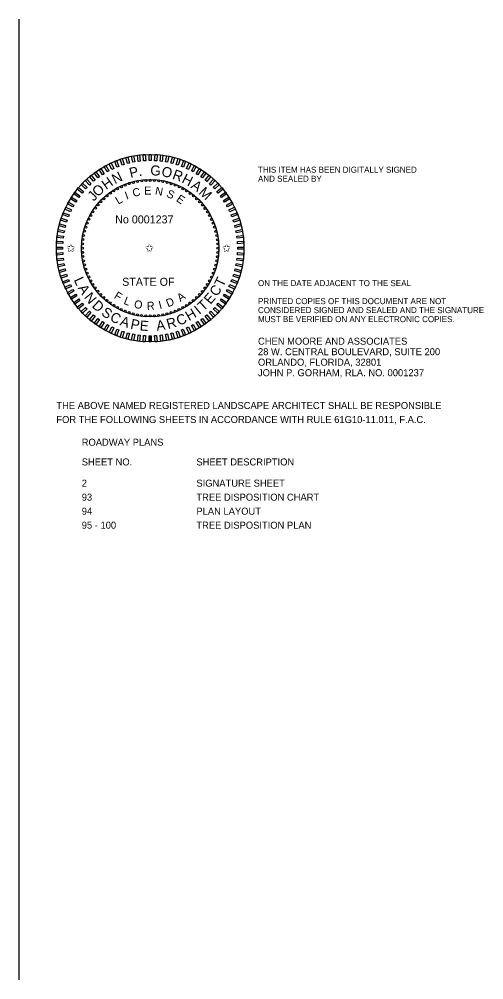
# Model space of a CAD drawing. Extents: x -811 to 10319, y -2309 to 9962.
# Drawn here: x -803.09 to -798.44, y -2187.21 to -2177.61 of the extents above; entities that cross this region are included whole.
import ezdxf

# ---------------------------------------------------------------- set-up
doc = ezdxf.new("R2010")
doc.units = 0
for name, color, linetype in [('PlotBorder_dp', 7, 'Continuous'), ('TextMinor', 7, 'Continuous'), ('TextMisc', 7, 'Continuous'), ('TextNotes', 7, 'Continuous'), ('TextShtNo', 7, 'Continuous')]:
    doc.layers.add(name, color=color, linetype=linetype)

msp = doc.modelspace()

# ---------------------------------------------------------------- linework, layer by layer
at = {"layer": 'TextMinor'}
for radius in [0.9375, 0.6875]:
    msp.add_circle((-801.777, -2179.9009), radius, dxfattribs=at)
at = {"layer": 'TextNotes'}
msp.add_line((-803.0858, -2187.2129), (-803.0858, -2177.6129), dxfattribs=at)
at = {"layer": 'TextShtNo'}
for p, q in [((-801.787, -2180.8384), (-801.7871, -2180.7759)), ((-801.777, -2180.8384), (-801.7771, -2180.7759)), ((-801.767, -2180.8383), (-801.7671, -2180.7758))]:
    msp.add_line(p, q, dxfattribs=at)
for points in [[(-802.0377, -2179.0655), (-802.0569, -2179.0718), (-802.0762, -2179.0124), (-802.057, -2179.0061)], [(-801.9847, -2179.0508), (-802.0042, -2179.0558), (-802.0198, -2178.9953), (-802.0002, -2178.9903)], [(-801.9309, -2179.0394), (-801.9507, -2179.0432), (-801.9624, -2178.9819), (-801.9426, -2178.9781)], [(-801.8765, -2179.0315), (-801.8965, -2179.034), (-801.9044, -2178.972), (-801.8843, -2178.9695)], [(-801.8217, -2179.0269), (-801.8419, -2179.0282), (-801.8458, -2178.9659), (-801.8256, -2178.9646)], [(-801.7668, -2179.0258), (-801.787, -2179.0258), (-801.787, -2178.9634), (-801.7668, -2178.9634)], [(-801.7118, -2179.0282), (-801.732, -2179.0269), (-801.7281, -2178.9646), (-801.7079, -2178.9659)], [(-801.6572, -2179.034), (-801.6772, -2179.0315), (-801.6694, -2178.9695), (-801.6493, -2178.9721)], [(-801.603, -2179.0432), (-801.6228, -2179.0395), (-801.6111, -2178.9781), (-801.5913, -2178.9819)], [(-801.5495, -2179.0559), (-801.569, -2179.0508), (-801.5535, -2178.9904), (-801.5339, -2178.9954)], [(-801.4969, -2179.0718), (-801.5161, -2179.0656), (-801.4968, -2179.0062), (-801.4776, -2179.0124)], [(-802.2372, -2179.1566), (-802.2543, -2179.1674), (-802.2877, -2179.1147), (-802.2707, -2179.1039)], [(-802.1896, -2179.1292), (-802.2073, -2179.1389), (-802.2373, -2179.0842), (-802.2197, -2179.0745)], [(-802.1403, -2179.1048), (-802.1586, -2179.1134), (-802.1852, -2179.0569), (-802.1669, -2179.0483)], [(-802.0896, -2179.0835), (-802.1084, -2179.091), (-802.1314, -2179.0329), (-802.1126, -2179.0255)], [(-801.4454, -2179.091), (-801.4641, -2179.0836), (-801.4411, -2179.0256), (-801.4224, -2179.033)], [(-801.3952, -2179.1135), (-801.4134, -2179.1049), (-801.3868, -2179.0484), (-801.3686, -2179.057)], [(-801.3465, -2179.139), (-801.3642, -2179.1293), (-801.3341, -2179.0745), (-801.3164, -2179.0843)], [(-801.2995, -2179.1675), (-801.3165, -2179.1567), (-801.2831, -2179.104), (-801.266, -2179.1148)], [(-802.3269, -2179.2202), (-802.3424, -2179.233), (-802.3822, -2179.1849), (-802.3667, -2179.172)], [(-802.283, -2179.187), (-802.2994, -2179.1988), (-802.3361, -2179.1483), (-802.3197, -2179.1365)], [(-801.2544, -2179.1989), (-801.2707, -2179.1871), (-801.234, -2179.1366), (-801.2177, -2179.1484)], [(-801.2113, -2179.2331), (-801.2269, -2179.2203), (-801.1871, -2179.1722), (-801.1715, -2179.185)], [(-802.4447, -2179.3353), (-802.4575, -2179.3508), (-802.5057, -2179.311), (-802.4928, -2179.2955)], [(-802.4078, -2179.2944), (-802.4217, -2179.3092), (-802.4672, -2179.2664), (-802.4534, -2179.2517)], [(-802.3685, -2179.256), (-802.3832, -2179.2698), (-802.426, -2179.2243), (-802.4113, -2179.2105)], [(-801.1705, -2179.27), (-801.1852, -2179.2562), (-801.1425, -2179.2106), (-801.1278, -2179.2245)], [(-801.1321, -2179.3093), (-801.1459, -2179.2946), (-801.1004, -2179.2518), (-801.0866, -2179.2666)], [(-801.0962, -2179.351), (-801.1091, -2179.3354), (-801.061, -2179.2956), (-801.0481, -2179.3112)], [(-802.5103, -2179.4234), (-802.5211, -2179.4404), (-802.5738, -2179.407), (-802.563, -2179.3899)], [(-802.4789, -2179.3783), (-802.4907, -2179.3946), (-802.5413, -2179.3579), (-802.5294, -2179.3416)], [(-801.063, -2179.3948), (-801.0749, -2179.3784), (-801.0244, -2179.3417), (-801.0125, -2179.3581)], [(-801.0327, -2179.4406), (-801.0435, -2179.4236), (-800.9908, -2179.3901), (-800.98, -2179.4071)], [(-802.5388, -2179.4704), (-802.5486, -2179.4881), (-802.6033, -2179.458), (-802.5936, -2179.4403)], [(-801.0052, -2179.4882), (-801.015, -2179.4706), (-800.9603, -2179.4405), (-800.9505, -2179.4582)], [(-802.5868, -2179.5693), (-802.5942, -2179.588), (-802.6523, -2179.5651), (-802.6448, -2179.5463)], [(-802.5644, -2179.5191), (-802.573, -2179.5373), (-802.6295, -2179.5108), (-802.6209, -2179.4925)], [(-800.9809, -2179.5375), (-800.9895, -2179.5193), (-800.933, -2179.4927), (-800.9244, -2179.5109)], [(-800.9596, -2179.5882), (-800.967, -2179.5695), (-800.909, -2179.5465), (-800.9016, -2179.5652)], [(-802.622, -2179.6734), (-802.627, -2179.6929), (-802.6875, -2179.6774), (-802.6824, -2179.6579)], [(-802.606, -2179.6208), (-802.6122, -2179.64), (-802.6716, -2179.6207), (-802.6654, -2179.6015)], [(-800.9416, -2179.6402), (-800.9478, -2179.621), (-800.8885, -2179.6017), (-800.8822, -2179.6209)], [(-800.9269, -2179.6931), (-800.9319, -2179.6736), (-800.8714, -2179.658), (-800.8664, -2179.6776)], [(-802.6438, -2179.7811), (-802.6463, -2179.8011), (-802.7083, -2179.7933), (-802.7058, -2179.7733)], [(-802.6346, -2179.7269), (-802.6384, -2179.7467), (-802.6997, -2179.735), (-802.6959, -2179.7152)], [(-800.9155, -2179.7469), (-800.9193, -2179.7271), (-800.858, -2179.7154), (-800.8542, -2179.7352)], [(-800.9075, -2179.8013), (-800.9101, -2179.7813), (-800.8481, -2179.7735), (-800.8456, -2179.7935)], [(-802.6496, -2179.8358), (-802.6509, -2179.8559), (-802.7132, -2179.852), (-802.7119, -2179.8318)], [(-800.903, -2179.8561), (-800.9043, -2179.8359), (-800.842, -2179.832), (-800.8407, -2179.8522)], [(-802.652, -2179.8907), (-802.652, -2179.9109), (-802.7144, -2179.9109), (-802.7144, -2179.8907)], [(-802.6509, -2179.9456), (-802.6496, -2179.9658), (-802.7119, -2179.9697), (-802.7132, -2179.9496)], [(-800.9043, -2179.966), (-800.903, -2179.9458), (-800.8407, -2179.9498), (-800.842, -2179.9699)], [(-800.9019, -2179.9111), (-800.9019, -2179.8909), (-800.8395, -2179.8909), (-800.8395, -2179.9111)], [(-802.6464, -2180.0004), (-802.6438, -2180.0205), (-802.7058, -2180.0283), (-802.7083, -2180.0083)], [(-802.6384, -2180.0548), (-802.6346, -2180.0747), (-802.6959, -2180.0864), (-802.6997, -2180.0665)], [(-800.9193, -2180.0748), (-800.9155, -2180.055), (-800.8542, -2180.0667), (-800.858, -2180.0865)], [(-800.9101, -2180.0206), (-800.9076, -2180.0006), (-800.8456, -2180.0084), (-800.8481, -2180.0285)], [(-802.627, -2180.1086), (-802.622, -2180.1282), (-802.6825, -2180.1437), (-802.6875, -2180.1241)], [(-800.9319, -2180.1283), (-800.9269, -2180.1088), (-800.8664, -2180.1243), (-800.8715, -2180.1439)], [(-802.6123, -2180.1616), (-802.6061, -2180.1808), (-802.6654, -2180.2001), (-802.6717, -2180.1809)], [(-802.5943, -2180.2135), (-802.5869, -2180.2323), (-802.6449, -2180.2553), (-802.6523, -2180.2365)], [(-800.9671, -2180.2325), (-800.9597, -2180.2137), (-800.9016, -2180.2367), (-800.9091, -2180.2554)], [(-800.9479, -2180.181), (-800.9417, -2180.1618), (-800.8823, -2180.1811), (-800.8885, -2180.2003)], [(-802.573, -2180.2642), (-802.5644, -2180.2825), (-802.6209, -2180.3091), (-802.6295, -2180.2908)], [(-802.5487, -2180.3135), (-802.5389, -2180.3312), (-802.5936, -2180.3613), (-802.6034, -2180.3436)], [(-801.0151, -2180.3313), (-801.0053, -2180.3137), (-800.9506, -2180.3437), (-800.9603, -2180.3614)], [(-800.9895, -2180.2827), (-800.9809, -2180.2644), (-800.9244, -2180.291), (-800.933, -2180.3092)], [(-802.5212, -2180.3611), (-802.5104, -2180.3782), (-802.5631, -2180.4116), (-802.5739, -2180.3946)], [(-802.4909, -2180.407), (-802.479, -2180.4233), (-802.5295, -2180.46), (-802.5414, -2180.4437)], [(-801.075, -2180.4234), (-801.0632, -2180.4071), (-801.0126, -2180.4438), (-801.0245, -2180.4601)], [(-801.0436, -2180.3783), (-801.0328, -2180.3613), (-800.9801, -2180.3947), (-800.9909, -2180.4118)], [(-802.4577, -2180.4508), (-802.4448, -2180.4663), (-802.4929, -2180.5061), (-802.5058, -2180.4906)], [(-802.4218, -2180.4924), (-802.408, -2180.5072), (-802.4535, -2180.5499), (-802.4673, -2180.5352)], [(-802.3834, -2180.5318), (-802.3687, -2180.5456), (-802.4114, -2180.5911), (-802.4261, -2180.5773)], [(-801.1854, -2180.5457), (-801.1707, -2180.5319), (-801.1279, -2180.5774), (-801.1426, -2180.5912)], [(-801.1461, -2180.5073), (-801.1322, -2180.4926), (-801.0867, -2180.5353), (-801.1005, -2180.55)], [(-801.1092, -2180.4665), (-801.0964, -2180.4509), (-801.0482, -2180.4907), (-801.0611, -2180.5063)], [(-802.3426, -2180.5686), (-802.327, -2180.5815), (-802.3668, -2180.6296), (-802.3824, -2180.6167)], [(-802.2995, -2180.6028), (-802.2832, -2180.6147), (-802.3199, -2180.6652), (-802.3362, -2180.6533)], [(-802.2544, -2180.6342), (-802.2374, -2180.645), (-802.2708, -2180.6978), (-802.2879, -2180.6869)], [(-801.3167, -2180.6451), (-801.2996, -2180.6343), (-801.2662, -2180.687), (-801.2832, -2180.6979)], [(-801.2709, -2180.6148), (-801.2545, -2180.6029), (-801.2178, -2180.6534), (-801.2342, -2180.6653)], [(-801.227, -2180.5816), (-801.2115, -2180.5687), (-801.1717, -2180.6168), (-801.1872, -2180.6297)], [(-802.2074, -2180.6628), (-802.1897, -2180.6725), (-802.2198, -2180.7272), (-802.2375, -2180.7175)], [(-802.1587, -2180.6883), (-802.1405, -2180.6969), (-802.1671, -2180.7534), (-802.1853, -2180.7448)], [(-802.1085, -2180.7107), (-802.0898, -2180.7181), (-802.1128, -2180.7762), (-802.1315, -2180.7688)], [(-802.057, -2180.7299), (-802.0378, -2180.7362), (-802.0571, -2180.7955), (-802.0763, -2180.7893)], [(-801.5162, -2180.7362), (-801.497, -2180.73), (-801.4777, -2180.7894), (-801.4969, -2180.7956)], [(-801.4643, -2180.7182), (-801.4455, -2180.7108), (-801.4225, -2180.7688), (-801.4413, -2180.7763)], [(-801.4136, -2180.697), (-801.3953, -2180.6884), (-801.3687, -2180.7449), (-801.387, -2180.7535)], [(-801.3643, -2180.6726), (-801.3466, -2180.6628), (-801.3166, -2180.7176), (-801.3342, -2180.7273)], [(-802.0044, -2180.7459), (-801.9849, -2180.7509), (-802.0004, -2180.8114), (-802.02, -2180.8064)], [(-801.9509, -2180.7585), (-801.9311, -2180.7623), (-801.9428, -2180.8236), (-801.9626, -2180.8198)], [(-801.8967, -2180.7677), (-801.8767, -2180.7703), (-801.8845, -2180.8322), (-801.9046, -2180.8297)], [(-801.8421, -2180.7735), (-801.8219, -2180.7748), (-801.8258, -2180.8371), (-801.846, -2180.8358)], [(-801.7871, -2180.7759), (-801.767, -2180.7759), (-801.767, -2180.8383), (-801.7871, -2180.8383)], [(-801.7322, -2180.7748), (-801.712, -2180.7735), (-801.7081, -2180.8359), (-801.7283, -2180.8371)], [(-801.6774, -2180.7703), (-801.6574, -2180.7677), (-801.6495, -2180.8297), (-801.6696, -2180.8322)], [(-801.623, -2180.7623), (-801.6032, -2180.7585), (-801.5915, -2180.8199), (-801.6113, -2180.8236)], [(-801.5692, -2180.7509), (-801.5497, -2180.7459), (-801.5341, -2180.8064), (-801.5537, -2180.8114)]]:
    msp.add_lwpolyline(points, close=True, dxfattribs=at)
for centre in [(-802.0649, -2179.2876), (-802.0258, -2179.2708), (-801.9858, -2179.2564), (-801.9449, -2179.2445), (-801.9033, -2179.2353), (-801.8613, -2179.2287), (-801.8189, -2179.2247), (-801.7764, -2179.2234), (-801.7338, -2179.2248), (-801.6915, -2179.2288), (-801.6495, -2179.2355), (-801.6079, -2179.2448), (-801.5671, -2179.2567), (-801.527, -2179.2712), (-801.488, -2179.2881), (-802.2084, -2179.3785), (-802.1747, -2179.3525), (-802.1395, -2179.3286), (-802.1028, -2179.3069), (-801.4501, -2179.3075), (-801.4135, -2179.3292), (-801.3783, -2179.3531), (-801.3447, -2179.3792), (-802.2986, -2179.4686), (-802.2704, -2179.4367), (-802.2403, -2179.4066), (-801.3128, -2179.4074), (-801.2827, -2179.4375), (-801.2546, -2179.4695), (-802.3703, -2179.574), (-802.3487, -2179.5374), (-802.3247, -2179.5022), (-801.2285, -2179.5031), (-801.2046, -2179.5383), (-801.183, -2179.575), (-802.4066, -2179.651), (-802.3897, -2179.6119), (-801.1637, -2179.6129), (-801.1468, -2179.652), (-802.4423, -2179.7734), (-802.433, -2179.7318), (-802.4211, -2179.691), (-801.1325, -2179.6921), (-801.1206, -2179.7329), (-801.1114, -2179.7745), (-802.453, -2179.8578), (-802.449, -2179.8154), (-801.1048, -2179.8165), (-801.1008, -2179.8589), (-802.4544, -2179.9003), (-802.4531, -2179.9428), (-801.1009, -2179.944), (-801.0995, -2179.9014), (-802.4491, -2179.9852), (-802.4425, -2180.0273), (-802.4333, -2180.0688), (-801.1209, -2180.0699), (-801.1116, -2180.0284), (-801.1049, -2179.9863), (-802.4214, -2180.1097), (-802.4071, -2180.1497), (-801.1473, -2180.1508), (-801.1328, -2180.1108), (-802.3902, -2180.1888), (-802.3709, -2180.2267), (-802.3493, -2180.2634), (-801.2052, -2180.2644), (-801.1836, -2180.2277), (-801.1642, -2180.1898), (-802.3254, -2180.2986), (-802.2993, -2180.3323), (-801.2553, -2180.3331), (-801.2292, -2180.2995), (-802.2712, -2180.3642), (-802.2411, -2180.3943), (-802.2092, -2180.4225), (-802.1756, -2180.4486), (-801.3792, -2180.4493), (-801.3456, -2180.4232), (-801.3136, -2180.3951), (-801.2835, -2180.365), (-802.1404, -2180.4726), (-802.1038, -2180.4943), (-802.0659, -2180.5136), (-802.0269, -2180.5306), (-801.9868, -2180.545), (-801.5681, -2180.5454), (-801.5281, -2180.531), (-801.489, -2180.5141), (-801.4511, -2180.4948), (-801.4144, -2180.4732), (-801.946, -2180.5569), (-801.9044, -2180.5662), (-801.8624, -2180.5729), (-801.8201, -2180.577), (-801.777, -2180.5784), (-801.735, -2180.577), (-801.6926, -2180.5731), (-801.6506, -2180.5664), (-801.609, -2180.5572)]:
    msp.add_circle(centre, 0.01, dxfattribs=at)

# ---------------------------------------------------------------- texts
at = {"layer": 'PlotBorder_dp'}
for s, height, p in [('THIS ITEM HAS BEEN DIGITALLY SIGNED ', 0.06, (-800.6993, -2179.147)), ('AND SEALED BY', 0.06, (-800.6993, -2179.237)), ('ON THE DATE ADJACENT TO THE SEAL', 0.06, (-800.6993, -2180.2804)), ('PRINTED COPIES OF THIS DOCUMENT ARE NOT ', 0.06, (-800.6993, -2180.4604)), ('CONSIDERED SIGNED AND SEALED AND THE SIGNATURE ', 0.06, (-800.6993, -2180.5504)), ('MUST BE VERIFIED ON ANY ELECTRONIC COPIES.', 0.06, (-800.6993, -2180.6404)), ('CHEN MOORE AND ASSOCIATES', 0.07, (-800.6993, -2180.8657)), ('28 W. CENTRAL BOULEVARD, SUITE 200', 0.07, (-800.6993, -2180.9707)), ('ORLANDO, FLORIDA, 32801', 0.07, (-800.6993, -2181.0757)), ('JOHN P. GORHAM, RLA. NO. 0001237', 0.07, (-800.6993, -2181.1807)), ('THE ABOVE NAMED REGISTERED LANDSCAPE ARCHITECT SHALL BE RESPONSIBLE ', 0.07, (-802.7145, -2181.5084)), ('FOR THE FOLLOWING SHEETS IN ACCORDANCE WITH RULE 61G10-11.011, F.A.C.', 0.07, (-802.7145, -2181.6484)), ('ROADWAY PLANS', 0.07, (-802.4607, -2181.8755))]:
    msp.add_text(s, height=height, dxfattribs=at).set_placement(p)
at = {"layer": 'TextMisc'}
for s, p in [('SHEET NO.', (-802.4607, -2182.0725)), ('SHEET DESCRIPTION', (-801.3148, -2182.0725)), ('2', (-802.4607, -2182.2847)), ('SIGNATURE SHEET', (-801.3148, -2182.2847)), ('93', (-802.4607, -2182.4247)), ('TREE DISPOSITION CHART', (-801.3148, -2182.4247)), ('94', (-802.4607, -2182.5647)), ('PLAN LAYOUT', (-801.3148, -2182.5647)), ('95 - 100', (-802.4607, -2182.7047)), ('TREE DISPOSITION PLAN', (-801.3148, -2182.7047))]:
    msp.add_text(s, height=0.07, dxfattribs=at).set_placement(p)
at = {"layer": 'TextShtNo'}
for s, height, rotation, p in [('P', 0.1, 13.27214, (-801.9727, -2179.1996)), ('G', 0.1, 357.67775, (-801.7769, -2179.1728)), ('O', 0.1, 349.14372, (-801.6689, -2179.1808)), ('H', 0.1, 34.8941, (-802.2173, -2179.321)), ('N', 0.1, 26.60166, (-802.1291, -2179.2636)), ('.', 0.1, 6.53189, (-801.889, -2179.1814)), ('R', 0.1, 340.48286, (-801.5617, -2179.2053)), ('H', 0.1, 332.66151, (-801.469, -2179.2411)), ('O', 0.1, 43.55496, (-802.2996, -2179.394)), ('E', 0.08, 0.41861, (-801.8367, -2179.3658)), ('N', 0.08, 349.29143, (-801.7323, -2179.3643)), ('A', 0.1, 324.36906, (-801.3771, -2179.2924)), ('M', 0.1, 316.60207, (-801.2985, -2179.352)), ('J', 0.1, 48.19946, (-802.3389, -2179.4379)), ('L', 0.08, 30.40215, (-802.0961, -2179.4672)), ('I', 0.08, 20.01168, (-802.0126, -2179.4168)), ('C', 0.08, 12.20255, (-801.9447, -2179.3893)), ('S', 0.08, 337.02207, (-801.6193, -2179.3861)), ('E', 0.08, 325.86633, (-801.5227, -2179.4263)), ('L', 0.1, 295.24283, (-802.5424, -2180.2178)), ('T', 0.1, 64.19548, (-801.0493, -2180.2969)), ('A', 0.1, 301.50595, (-802.5032, -2180.2994)), ('N', 0.1, 309.27295, (-802.4427, -2180.3939)), ('F', 0.08, 328.72408, (-802.145, -2180.3975)), ('A', 0.08, 34.49917, (-801.4751, -2180.4403)), ('E', 0.1, 49.41645, (-801.1744, -2180.4694)), ('C', 0.1, 56.45868, (-801.1092, -2180.3912)), ('D', 0.1, 317.52311, (-802.3651, -2180.4843)), ('L', 0.08, 339.29159, (-802.0477, -2180.4565)), ('O', 0.08, 349.68206, (-801.943, -2180.4962)), ('R', 0.08, 2.33977, (-801.8085, -2180.5182)), ('I', 0.08, 14.20366, (-801.681, -2180.5115)), ('D', 0.08, 22.01279, (-801.5989, -2180.4928)), ('T', 0.1, 42.59164, (-801.2462, -2180.537)), ('S', 0.1, 326.00279, (-802.2726, -2180.5647)), ('H', 0.1, 30.766, (-801.3878, -2180.6322)), ('I', 0.1, 39.05844, (-801.2864, -2180.5685)), ('C', 0.1, 333.07522, (-802.1871, -2180.6207)), ('A', 0.1, 340.81202, (-802.0865, -2180.6693)), ('P', 0.1, 348.57901, (-801.9798, -2180.7041)), ('E', 0.1, 355.31927, (-801.8841, -2180.7224)), ('A', 0.1, 7.44085, (-801.7092, -2180.7266)), ('R', 0.1, 15.20785, (-801.5982, -2180.7098)), ('C', 0.1, 23.0292, (-801.4898, -2180.678))]:
    msp.add_text(s, height=height, rotation=rotation, dxfattribs=at).set_placement(p)
for s, p in [('No 0001237', (-802.1267, -2179.6536)), ('✩', (-802.6119, -2179.9388)), ('✩', (-801.8272, -2179.9388)), ('✩', (-801.0554, -2179.9388)), ('STATE OF', (-802.0567, -2180.2771))]:
    msp.add_text(s, height=0.08, dxfattribs=at).set_placement(p)

doc.saveas('drawing.dxf')
